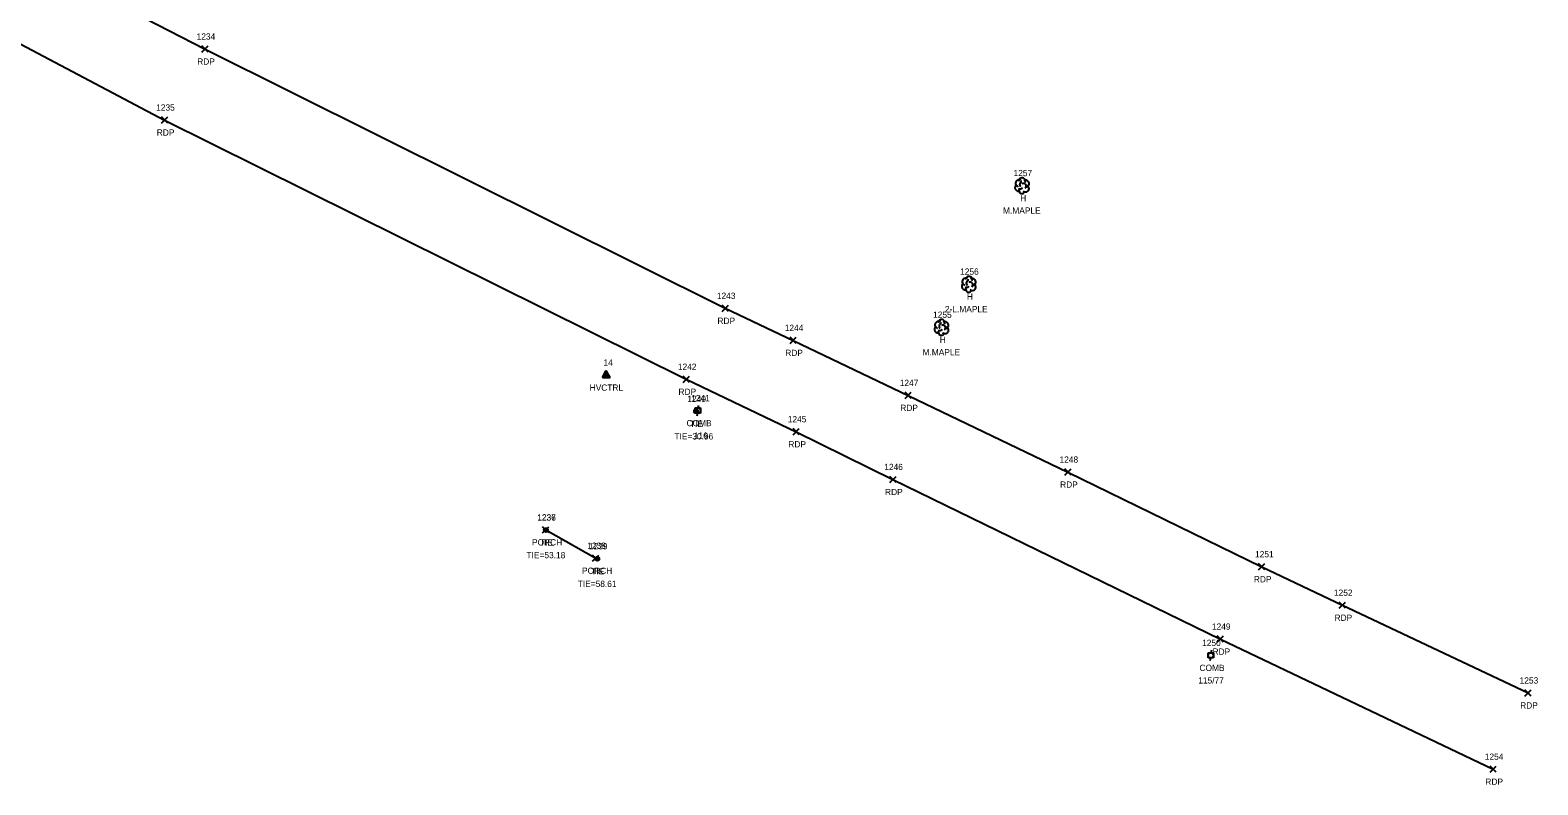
# Model space of a CAD drawing. Extents: x 1560235 to 1566224, y 675811 to 678683.
# Drawn here: x 1564966.9 to 1565449.1, y 675811.1 to 676052.4 of the extents above; entities that cross this region are included whole.
import ezdxf

# ---------------------------------------------------------------- set-up
doc = ezdxf.new("R2010")
doc.units = 0
for name, color, linetype in [('C_A', 7, 'Continuous'), ('C_C', 7, 'Continuous'), ('C_I', 7, 'Continuous'), ('CBP', 7, 'Continuous'), ('CPSM', 7, 'Continuous'), ('L_A', 7, 'Continuous'), ('L_C', 7, 'Continuous'), ('L_I', 7, 'Continuous'), ('L_TIC', 7, 'Continuous'), ('LBF', 7, 'Continuous'), ('LTD', 7, 'Continuous'), ('P_A', 7, 'Continuous'), ('P_I', 7, 'Continuous'), ('P_TIC', 7, 'Continuous'), ('PET', 7, 'Continuous'), ('U_A', 7, 'Continuous'), ('U_C', 7, 'Continuous'), ('U_I', 7, 'Continuous'), ('UP', 7, 'Continuous')]:
    doc.layers.add(name, color=color, linetype=linetype)

msp = doc.modelspace()

# ---------------------------------------------------------------- linework, layer by layer
at = {"layer": 'CBP'}
for centre, radius in [((1565179.85, 675930.53), 0.625), ((1565179.85, 675930.53), 0.0833), ((1565131.83, 675892.57), 0.625), ((1565131.83, 675892.57), 0.0833), ((1565148.28, 675883.38), 0.625), ((1565148.28, 675883.38), 0.0833)]:
    msp.add_circle(centre, radius, dxfattribs=at)
at = {"layer": 'CPSM'}
for p, q in [((1565149.89, 675941.4), (1565151.14, 675943.56)), ((1565149.89, 675941.4), (1565151.14, 675942.12)), ((1565149.89, 675941.4), (1565152.39, 675941.4)), ((1565152.39, 675941.4), (1565151.14, 675943.56)), ((1565151.14, 675942.12), (1565151.14, 675943.56)), ((1565151.14, 675942.12), (1565151.14, 675942.12)), ((1565151.14, 675942.12), (1565152.39, 675941.4))]:
    msp.add_line(p, q, dxfattribs=at)
at = {"layer": 'L_TIC'}
for points in [[(1565130.77, 675891.64), (1565132.77, 675893.64)], [(1565132.77, 675891.64), (1565130.77, 675893.64)], [(1565146.77, 675882.57), (1565148.77, 675884.57)], [(1565148.77, 675882.57), (1565146.77, 675884.57)]]:
    msp.add_lwpolyline(points, dxfattribs=at)
at = {"layer": 'LBF'}
msp.add_lwpolyline([(1565131.77, 675892.64), (1565147.77, 675883.57)], dxfattribs=at)
at = {"layer": 'LTD'}
for p, q in [((1565284.12, 676002.74), (1565284.12, 676002.74)), ((1565284.12, 676002.74), (1565284.12, 676002.74)), ((1565267.08, 675971.22), (1565267.08, 675971.22)), ((1565267.08, 675971.22), (1565267.08, 675971.22)), ((1565258.37, 675957.44), (1565258.37, 675957.44)), ((1565258.37, 675957.44), (1565258.37, 675957.44))]:
    msp.add_line(p, q, dxfattribs=at)
for centre in [(1565284.16, 676004.18), (1565267.12, 675972.66), (1565258.42, 675958.87)]:
    msp.add_arc(centre, 1.05, 335.5272, 180.9563, dxfattribs=at)
for centre, major_axis, ratio, start_param, end_param in [((1565283.03, 676002.03), (0.58, -1.04), 0.959034, 3.141593, 6.283185), ((1565283.33, 676003.41), (1.21, -0.51), 0.895232, 1.570796, 4.712389), ((1565283.91, 676003.2), (-0.208, -0.792), 0.645439, 3.141593, 6.283185), ((1565284.62, 676002.58), (-0.5, 0.667), 0.989748, 3.141593, 6.283185), ((1565285.12, 676001.91), (-1.09, 0.79), 0.841452, 1.570796, 4.712389), ((1565285.16, 676003.33), (-1.14, -0.48), 0.949671, 1.570796, 4.712389), ((1565284.12, 676001.24), (0.26, 1.06), 0.942809, 1.570796, 4.712389), ((1565283.66, 676001.99), (-0.625, -0.083), 0.423636, 0, 3.141593), ((1565265.99, 675970.52), (0.58, -1.04), 0.959034, 3.141593, 6.283185), ((1565266.29, 675971.89), (1.21, -0.51), 0.895232, 1.570796, 4.712389), ((1565267.08, 675969.72), (0.26, 1.06), 0.942809, 1.570796, 4.712389), ((1565266.62, 675970.47), (-0.625, -0.083), 0.423636, 0, 3.141593), ((1565266.87, 675971.68), (-0.208, -0.792), 0.645439, 3.141593, 6.283185), ((1565267.58, 675971.06), (-0.5, 0.667), 0.989748, 3.141593, 6.283185), ((1565268.08, 675970.39), (-1.09, 0.79), 0.841452, 1.570796, 4.712389), ((1565268.12, 675971.81), (-1.14, -0.48), 0.949671, 1.570796, 4.712389), ((1565257.58, 675958.1), (1.21, -0.51), 0.895232, 1.570796, 4.712389), ((1565259.42, 675958.02), (-1.14, -0.48), 0.949671, 1.570796, 4.712389), ((1565257.29, 675956.73), (0.58, -1.04), 0.959034, 3.141593, 6.283185), ((1565258.37, 675955.94), (0.26, 1.06), 0.942809, 1.570796, 4.712389), ((1565257.92, 675956.69), (-0.625, -0.083), 0.423636, 0, 3.141593), ((1565258.17, 675957.9), (-0.208, -0.792), 0.645439, 3.141593, 6.283185), ((1565258.87, 675957.27), (-0.5, 0.667), 0.989748, 3.141593, 6.283185), ((1565259.37, 675956.6), (-1.09, 0.79), 0.841452, 1.570796, 4.712389)]:
    msp.add_ellipse(centre, major_axis=major_axis, ratio=ratio, start_param=start_param, end_param=end_param, dxfattribs=at)
at = {"layer": 'P_TIC'}
for points in [[(1565021.8, 676045.4), (1565023.8, 676047.4)], [(1565023.8, 676045.4), (1565021.8, 676047.4)], [(1565008.86, 676022.7), (1565010.86, 676024.7)], [(1565010.86, 676022.7), (1565008.86, 676024.7)], [(1565188.22, 675962.48), (1565190.22, 675964.48)], [(1565190.22, 675962.48), (1565188.22, 675964.48)], [(1565209.93, 675952.23), (1565211.93, 675954.23)], [(1565211.93, 675952.23), (1565209.93, 675954.23)], [(1565175.75, 675939.8), (1565177.75, 675941.8)], [(1565177.75, 675939.8), (1565175.75, 675941.8)], [(1565246.72, 675934.64), (1565248.72, 675936.64)], [(1565248.72, 675934.64), (1565246.72, 675936.64)], [(1565210.9, 675923.01), (1565212.9, 675925.01)], [(1565212.9, 675923.01), (1565210.9, 675925.01)], [(1565297.84, 675910.11), (1565299.84, 675912.11)], [(1565299.84, 675910.11), (1565297.84, 675912.11)], [(1565241.83, 675907.75), (1565243.83, 675909.75)], [(1565243.83, 675907.75), (1565241.83, 675909.75)], [(1565359.81, 675879.84), (1565361.81, 675881.84)], [(1565361.81, 675879.84), (1565359.81, 675881.84)], [(1565385.62, 675867.54), (1565387.62, 675869.54)], [(1565387.62, 675867.54), (1565385.62, 675869.54)], [(1565346.6, 675856.7), (1565348.6, 675858.7)], [(1565348.6, 675856.7), (1565346.6, 675858.7)], [(1565445.01, 675839.48), (1565447.01, 675841.48)], [(1565447.01, 675839.48), (1565445.01, 675841.48)], [(1565433.87, 675815.1), (1565435.87, 675817.1)], [(1565435.87, 675815.1), (1565433.87, 675817.1)]]:
    msp.add_lwpolyline(points, dxfattribs=at)
at = {"layer": 'PET'}
for points in [[(1564479.9, 676381.34), (1564541.44, 676339.01), (1564575.62, 676315.99), (1564622.31, 676284.58), (1564662.66, 676258.14), (1564691.94, 676238.69), (1564734.09, 676211.56), (1564779.77, 676182.19), (1564799.71, 676170.07), (1564844.36, 676143.51), (1564865.94, 676131.61), (1564905.17, 676109.3), (1564928.6, 676096.14), (1564958.23, 676080.1), (1564973.05, 676072.07), (1565022.8, 676046.4), (1565189.22, 675963.48), (1565210.93, 675953.23), (1565247.72, 675935.64), (1565298.84, 675911.11), (1565360.81, 675880.84), (1565386.62, 675868.54), (1565446.01, 675840.48)], [(1564464.54, 676360.01), (1564490.91, 676342.29), (1564528.25, 676316.59), (1564542.68, 676306.76), (1564567.93, 676289.68), (1564606.82, 676263.66), (1564639.1, 676242.21), (1564676.57, 676217.4), (1564712.73, 676194.04), (1564741.2, 676175.76), (1564762.18, 676162.52), (1564808.53, 676134.4), (1564846.34, 676112.74), (1564898.03, 676083.46), (1564921.49, 676070.39), (1564960.02, 676050.01), (1565009.86, 676023.7), (1565176.75, 675940.8), (1565211.9, 675924.01), (1565242.83, 675908.75), (1565347.6, 675857.7), (1565434.87, 675816.1)]]:
    msp.add_lwpolyline(points, dxfattribs=at)
at = {"layer": 'UP'}
for p, q in [((1565179.61, 675929.95), (1565179.61, 675931.61)), ((1565179.61, 675931.61), (1565181.28, 675931.61)), ((1565180.7, 675932.45), (1565180.45, 675931.61)), ((1565180.45, 675930.78), (1565180.45, 675930.78)), ((1565181.28, 675931.61), (1565181.28, 675929.95)), ((1565181.28, 675929.95), (1565179.61, 675929.95)), ((1565180.2, 675929.11), (1565180.45, 675929.95)), ((1565343.7, 675851.67), (1565343.7, 675853.33)), ((1565343.7, 675853.33), (1565345.37, 675853.33)), ((1565344.78, 675854.17), (1565344.53, 675853.33)), ((1565345.37, 675853.33), (1565345.37, 675851.67)), ((1565345.37, 675851.67), (1565343.7, 675851.67)), ((1565344.28, 675850.83), (1565344.53, 675851.67)), ((1565344.53, 675852.5), (1565344.53, 675852.5))]:
    msp.add_line(p, q, dxfattribs=at)
for centre in [(1565180.45, 675930.78), (1565344.53, 675852.5)]:
    msp.add_circle(centre, 0.833, dxfattribs=at)

# ---------------------------------------------------------------- texts
at = {"layer": 'C_A'}
for s, p in [('HVCTRL', (1565145.84, 675937.12)), ('TIE', (1565177.93, 675925.53)), ('TIE', (1565129.91, 675887.57)), ('TIE', (1565146.35, 675878.38))]:
    msp.add_text(s, height=2, dxfattribs=at).set_placement(p)
at = {"layer": 'C_C'}
for s, p in [('TIE=30.96', (1565172.95, 675921.53)), ('TIE=53.18', (1565125.63, 675883.57)), ('TIE=58.61', (1565142.02, 675874.38))]:
    msp.add_text(s, height=2, dxfattribs=at).set_placement(p)
at = {"layer": 'C_I'}
for s, p in [('14', (1565150.25, 675945.12)), ('1240', (1565177.08, 675933.53)), ('1236', (1565129.08, 675895.57)), ('1239', (1565145.57, 675886.38))]:
    msp.add_text(s, height=2, dxfattribs=at).set_placement(p)
at = {"layer": 'L_A'}
for s, p in [('H', (1565283.55, 675997.74)), ('H', (1565266.51, 675966.22)), ('H', (1565257.81, 675952.44)), ('PORCH', (1565127.39, 675887.64)), ('PORCH', (1565143.39, 675878.57))]:
    msp.add_text(s, height=2, dxfattribs=at).set_placement(p)
at = {"layer": 'L_C'}
for s, p in [('M.MAPLE', (1565278.06, 675993.74)), ('2-L.MAPLE', (1565259.47, 675962.22)), ('M.MAPLE', (1565252.31, 675948.44))]:
    msp.add_text(s, height=2, dxfattribs=at).set_placement(p)
at = {"layer": 'L_I'}
for s, p in [('1257', (1565281.43, 676005.74)), ('1256', (1565264.33, 675974.22)), ('1255', (1565255.68, 675960.44)), ('1237', (1565129.08, 675895.64)), ('1238', (1565145.07, 675886.57))]:
    msp.add_text(s, height=2, dxfattribs=at).set_placement(p)
at = {"layer": 'P_A'}
for p in [(1565020.29, 676041.4), (1565007.35, 676018.7), (1565186.71, 675958.48), (1565208.42, 675948.23), (1565174.24, 675935.8), (1565245.21, 675930.64), (1565209.39, 675919.01), (1565296.33, 675906.11), (1565240.32, 675903.75), (1565358.3, 675875.84), (1565384.11, 675863.54), (1565345.09, 675852.7), (1565443.5, 675835.48), (1565432.36, 675811.1)]:
    msp.add_text('RDP', height=2, dxfattribs=at).set_placement(p)
at = {"layer": 'P_I'}
for s, p in [('1234', (1565020.11, 676049.4)), ('1235', (1565007.17, 676026.7)), ('1243', (1565186.53, 675966.48)), ('1244', (1565208.24, 675956.23)), ('1242', (1565174.06, 675943.8)), ('1247', (1565245.03, 675938.64)), ('1245', (1565209.2, 675927.01)), ('1248', (1565296.15, 675914.11)), ('1246', (1565240.08, 675911.75)), ('1251', (1565358.69, 675883.84)), ('1252', (1565383.93, 675871.54)), ('1249', (1565344.9, 675860.7)), ('1253', (1565443.32, 675843.48)), ('1254', (1565432.18, 675819.1))]:
    msp.add_text(s, height=2, dxfattribs=at).set_placement(p)
at = {"layer": 'U_A'}
for p in [(1565176.83, 675925.78), (1565340.92, 675847.5)]:
    msp.add_text('COMB', height=2, dxfattribs=at).set_placement(p)
at = {"layer": 'U_C'}
for s, p in [('116', (1565179.16, 675921.78)), ('115/77', (1565340.53, 675843.5))]:
    msp.add_text(s, height=2, dxfattribs=at).set_placement(p)
at = {"layer": 'U_I'}
for s, p in [('1241', (1565178.32, 675933.78)), ('1250', (1565341.75, 675855.5))]:
    msp.add_text(s, height=2, dxfattribs=at).set_placement(p)

doc.saveas('drawing.dxf')
